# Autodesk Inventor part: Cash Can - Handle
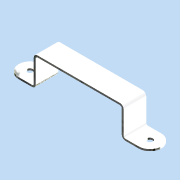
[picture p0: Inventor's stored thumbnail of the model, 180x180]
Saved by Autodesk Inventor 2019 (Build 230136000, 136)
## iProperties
Created: 2005-02
Part Number: Cash Can - Handle
Document SubType Name: Sheet Metal
Designer: floress
Material: Aluminum 6061
Density: 2.7 g/cm^3
Sheet Metal Rule: Default
Appearance: Aluminum - Flat
Flat Pattern Width: 2 cm
Flat Pattern Length: 17.1607 cm
Flat Pattern Area: 34.3214 cm^2
Sheet Metal Width: 20.000 mm
Sheet Metal Length: 171.607 mm
Sheet Metal Area: 3432.142 mm^2
Author: floress
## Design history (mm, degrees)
node "Face1"
  sketch "Sketch1"
    geometry: L1 (53.544, -10.397)-(38.544, -10.397); L2 (38.544, -10.397)-(38.544, 9.603); L3 (38.544, 9.603)-(53.544, 9.603); L4 (93.544, 42.531)-(93.544, -43.325) reference; A1 r 10 centre (53.544, -0.397) between (53.544, -10.397) and (53.544, 9.603); 2 further points
    constraints: 6 end point, 2 point on circle, 1 centre point, 1 coincident, 1 horizontal, 1 horizontal alignment, 1 midpoint, 1 parallel, 1 perpendicular
    dimensions: "d1" = 10 radius of A1; "d2" = 15 distance from line of L2 point (53.544, -0.397); "d3" = 40 distance from line of L4 point (53.544, -0.397)
workplane "Work Plane1"
node "Flange1"
node "Flange2"
workplane "Work Plane2"
node "Face2"
  sketch "Sketch4"
    geometry: L1 (-92.75, -44.119)-(-92.75, 43.325) reference; L2 (-52.75, -10.397)-(-37.75, -10.397); L3 (-37.75, -10.397)-(-37.75, 9.603); L4 (-37.75, 9.603)-(-52.75, 9.603); A1 r 10 centre (-52.75, -0.397) between (-52.75, 9.603) and (-52.75, -10.397); 1 further point
    constraints: 6 end point, 3 perpendicular, 2 point on circle, 2 tangent, 1 centre point, 1 horizontal alignment, 1 midpoint
    dimensions: "d19" = 20 diameter of A1; "d20" = 40 distance from line of L1 A1.centre; "d21" = 15 distance from line of A1.centre L3
node "Flange3"
bend "Bend5" dims "d34" = 1.5875 (= BendReliefWidth), "d35" = 0.79375 (= BendReliefDepth), "d36" = 3.175 (= MinimumRemnant), "d37" = 1.5875 (= BendRadius), "d38" = 1.5875 (= BendRadius), "d57" = 1.5875 (= Thickness), "SeamGap" = 0.01
hole "Hole1" diameter "d41" = 5; stored, may be unused: countersink angle "d45" = 90 deg, drill point angle "d47" = 118 deg; dims "d39" = 10, "d40" = 10, "d42" = 6, "d43" = 4, "d44" = 2, "d46" = 1.5875 (= Thickness)
hole "Hole2" diameter "d50" = 5; stored, may be unused: countersink angle "d54" = 90 deg, drill point angle "d56" = 118 deg; dims "d48" = 10, "d49" = 10, "d51" = 6, "d52" = 4, "d53" = 2, "d55" = 1.5875 (= Thickness)
body "Solid1"
node "Reference1"
face "Plate1" dims "d57" = 1.5875 (= Thickness)
sketch "Sketch2"
  geometry: L1 through (10, 0) direction (1, 0); L2 (20, 0)-(20, 25); L3 (20, 25)-(0, 25); L4 through (0, 12.5) direction (0, -1)
  constraints: 6 end point, 1 horizontal, 1 perpendicular, 1 vertical
face "Plate2" dims "d5" = 1.5875 (= BendReliefWidth), "d7" = 3.175 (= MinimumRemnant), "d9" = 25, "d10" = 90 deg, "d11" = 1.5875 (= BendRadius), "d57" = 1.5875 (= Thickness)
bend "Bend1" dims "d5" = 1.5875 (= BendReliefWidth), "d6" = 0.79375 (= BendReliefDepth), "d7" = 3.175 (= MinimumRemnant), "d8" = 1.5875 (= BendRadius), "d9" = 25, "d10" = 90 deg, "d11" = 1.5875 (= BendRadius), "d57" = 1.5875 (= Thickness), "SeamGap" = 0.01
sketch "Sketch3"
  geometry: L1 through (10, 0) direction (1, 0); L2 (20, 0)-(20, 70); L3 (20, 70)-(0, 70); L4 through (0, 35) direction (0, -1)
  constraints: 6 end point, 1 horizontal, 1 perpendicular, 1 vertical
face "Plate3" dims "d12" = 1.5875 (= BendReliefWidth), "d14" = 3.175 (= MinimumRemnant), "d16" = 70, "d17" = 90 deg, "d18" = 1.5875 (= BendRadius), "d57" = 1.5875 (= Thickness)
bend "Bend2" dims "d12" = 1.5875 (= BendReliefWidth), "d13" = 0.79375 (= BendReliefDepth), "d14" = 3.175 (= MinimumRemnant), "d15" = 1.5875 (= BendRadius), "d16" = 70, "d17" = 90 deg, "d18" = 1.5875 (= BendRadius), "d57" = 1.5875 (= Thickness), "SeamGap" = 0.01
node "Reference2"
face "Plate4" dims "d22" = 1.5875 (= BendRadius), "d23" = 1.5875 (= BendReliefWidth), "d25" = 3.175 (= MinimumRemnant), "d57" = 1.5875 (= Thickness)
bend "Bend3" dims "d22" = 1.5875 (= BendRadius), "d23" = 1.5875 (= BendReliefWidth), "d24" = 0.79375 (= BendReliefDepth), "d25" = 3.175 (= MinimumRemnant), "d26" = 1.5875 (= BendRadius), "d57" = 1.5875 (= Thickness), "SeamGap" = 0.01
sketch "Sketch5"
  geometry: L1 through (10, 0) direction (1, 0); L2 (20, 0)-(20, 25); L3 (20, 25)-(0, 25); L4 through (0, 12.5) direction (4.44e-17, -1)
  constraints: 6 end point, 1 horizontal, 1 perpendicular, 1 vertical
face "Plate5" dims "d27" = 1.5875 (= BendReliefWidth), "d29" = 3.175 (= MinimumRemnant), "d31" = 25, "d32" = 90 deg, "d33" = 1.5875 (= BendRadius), "d57" = 1.5875 (= Thickness)
bend "Bend4" dims "d27" = 1.5875 (= BendReliefWidth), "d28" = 0.79375 (= BendReliefDepth), "d29" = 3.175 (= MinimumRemnant), "d30" = 1.5875 (= BendRadius), "d31" = 25, "d32" = 90 deg, "d33" = 1.5875 (= BendRadius), "d57" = 1.5875 (= Thickness), "SeamGap" = 0.01
feature "Definition1"
other parameters: "Thickness" = 1.5875, "BendRadius" = 1.5875 (= Thickness), "BendReliefWidth" = 1.5875 (= Thickness), "BendReliefDepth" = 0.79375 (= 0.5 x Thickness), "CornerReliefSize" = 6.35 (= 4 x Thickness), "MinimumRemnant" = 3.175 (= 2 x Thickness), "TransitionRadius" = 1.5875 (= BendRadius), "d4" = 1.5875 (= BendRadius), "JacobiRadiusSize" = 1.5875 (= Thickness), "GapSize" = 1.5875 (= Thickness), "BendRadius" = 1.5875, "BendReliefDepth" = 0.79375, "BendReliefWidth" = 1.5875, "CornerReliefSize" = 6.35, "GapSize" = 1.5875, "JacobiRadiusSize" = 1.5875, "MinimumRemnant" = 3.175, "Thickness" = 1.5875, "TransitionRadius" = 1.5875
